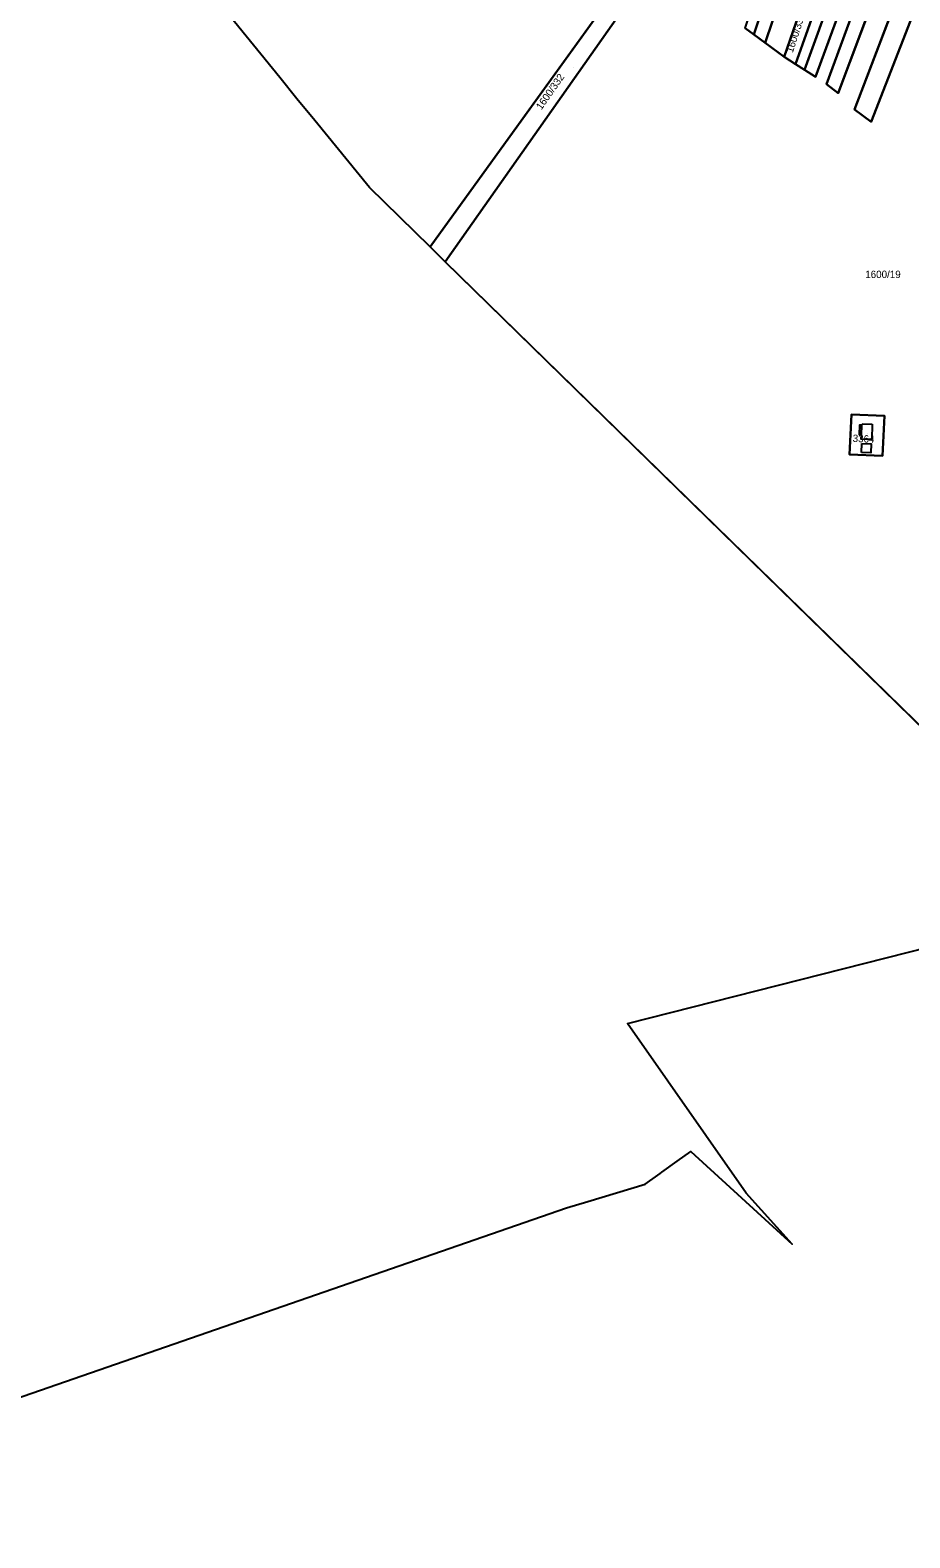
# Model space of a CAD drawing. Extents: x -262715 to -259381, y -1237238 to -1231182.
# Drawn here: x -262013.6 to -261773.9, y -1236768.6 to -1236357.8 of the extents above; entities that cross this region are included whole.
import ezdxf

# ---------------------------------------------------------------- set-up
doc = ezdxf.new("R2010")
doc.units = 0
for name, color, linetype in [('body_kn', 7, 'Continuous'), ('katuz_linie', 7, 'Continuous'), ('kladpar_druhypozemkov', 7, 'Continuous'), ('kladpar_hranice', 7, 'Continuous'), ('kladpar_parcelnecisla', 7, 'Continuous'), ('kladpar_plochy', 7, 'Continuous'), ('zappar_hrandruhpozemk', 7, 'Continuous'), ('zuob_linie', 7, 'Continuous'), ('zuob_plochy', 7, 'Continuous')]:
    doc.layers.add(name, color=color, linetype=linetype)

msp = doc.modelspace()

# ---------------------------------------------------------------- linework, layer by layer
at = {"layer": 'body_kn'}
for p, q in [((-261816.38, -1236359.01), (-261816.38, -1236359.01)), ((-261816.38, -1236359.01), (-261816.38, -1236359.01)), ((-261813.31, -1236361.3), (-261813.31, -1236361.3)), ((-261808.13, -1236365.09), (-261808.13, -1236365.09)), ((-261808.13, -1236365.09), (-261808.13, -1236365.09)), ((-261945.58, -1236370.74), (-261945.58, -1236370.74)), ((-261805.06, -1236367.11), (-261805.06, -1236367.11)), ((-261805.06, -1236367.11), (-261805.06, -1236367.11)), ((-261802.62, -1236368.65), (-261802.62, -1236368.65)), ((-261802.62, -1236368.65), (-261802.62, -1236368.65)), ((-261799.61, -1236370.59), (-261799.61, -1236370.59)), ((-261796.62, -1236372.52), (-261796.62, -1236372.52)), ((-261793.44, -1236375.02), (-261793.44, -1236375.02)), ((-261940.87, -1236376.52), (-261940.87, -1236376.52)), ((-261936.03, -1236382.46), (-261936.03, -1236382.46)), ((-261788.99, -1236379.43), (-261788.99, -1236379.43)), ((-261784.41, -1236382.82), (-261784.41, -1236382.82)), ((-261921.14, -1236400.73), (-261921.14, -1236400.73)), ((-261904.58, -1236416.92), (-261904.58, -1236416.92)), ((-261904.58, -1236416.92), (-261904.58, -1236416.92)), ((-261900.47, -1236420.93), (-261900.47, -1236420.93)), ((-261900.47, -1236420.93), (-261900.47, -1236420.93)), ((-261789.8, -1236462.53), (-261789.8, -1236462.53)), ((-261789.8, -1236462.53), (-261789.8, -1236462.53)), ((-261787.58, -1236465.44), (-261787.58, -1236465.44)), ((-261786.93, -1236465.47), (-261786.93, -1236465.47)), ((-261786.91, -1236465.07), (-261786.91, -1236465.07)), ((-261786.91, -1236465.07), (-261786.91, -1236465.07)), ((-261784.17, -1236465.2), (-261784.17, -1236465.2)), ((-261780.81, -1236462.96), (-261780.81, -1236462.96)), ((-261787.7, -1236468.04), (-261787.7, -1236468.04)), ((-261787.11, -1236469.27), (-261787.11, -1236469.27)), ((-261787.05, -1236468.07), (-261787.05, -1236468.07)), ((-261787.05, -1236468.07), (-261787.05, -1236468.07)), ((-261784.25, -1236469.35), (-261784.25, -1236469.35)), ((-261790.31, -1236473.43), (-261790.31, -1236473.43)), ((-261787.04, -1236472.92), (-261787.04, -1236472.92)), ((-261786.95, -1236470.43), (-261786.95, -1236470.43)), ((-261786.95, -1236470.43), (-261786.95, -1236470.43)), ((-261784.55, -1236473.01), (-261784.55, -1236473.01)), ((-261784.46, -1236470.52), (-261784.46, -1236470.52)), ((-261781.32, -1236473.84), (-261781.32, -1236473.84)), ((-261850.8, -1236628.52), (-261850.8, -1236628.52)), ((-261837.31, -1236666.04), (-261837.31, -1236666.04)), ((-261833.57, -1236663.38), (-261833.57, -1236663.38)), ((-261841.94, -1236669.33), (-261841.94, -1236669.33)), ((-261841.46, -1236668.99), (-261841.46, -1236668.99)), ((-261846.03, -1236672.24), (-261846.03, -1236672.24)), ((-261818.47, -1236674.69), (-261818.47, -1236674.69)), ((-261867.4, -1236678.73), (-261867.4, -1236678.73)), ((-261861.65, -1236676.99), (-261861.65, -1236676.99)), ((-261805.93, -1236688.64), (-261805.93, -1236688.64))]:
    msp.add_line(p, q, dxfattribs=at)
at = {"layer": 'katuz_linie'}
msp.add_lwpolyline([(-262126.94, -1236768.63), (-261867.4, -1236678.73), (-261861.65, -1236676.99), (-261846.03, -1236672.24), (-261841.94, -1236669.33), (-261841.46, -1236668.99), (-261837.31, -1236666.04), (-261833.57, -1236663.38), (-261805.93, -1236688.64), (-261818.47, -1236674.69), (-261850.8, -1236628.52), (-261721.65, -1236595.68), (-261900.47, -1236420.93), (-261904.58, -1236416.92), (-261921.14, -1236400.73), (-261936.03, -1236382.46), (-261940.87, -1236376.52), (-261945.58, -1236370.74), (-261959.9, -1236353.15)], dxfattribs=at)
at = {"layer": 'kladpar_druhypozemkov'}
for p, q in [((-261865.41, -1236367.96), (-261865.41, -1236367.96)), ((-261780.83, -1236423.34), (-261780.83, -1236423.34)), ((-261785.44, -1236467.68), (-261785.44, -1236467.68))]:
    msp.add_line(p, q, dxfattribs=at)
at = {"layer": 'kladpar_hranice'}
for p, q in [((-261808.13, -1236365.09), (-261801.51, -1236346.05)), ((-261802.62, -1236368.65), (-261805.06, -1236367.11)), ((-261900.47, -1236420.93), (-261904.58, -1236416.92))]:
    msp.add_line(p, q, dxfattribs=at)
for points in [[(-261768.56, -1236215.73), (-261783.95, -1236261.61), (-261786.4, -1236268.98), (-261799, -1236306.82), (-261816.38, -1236359.01), (-261818.71, -1236357.31), (-261806.34, -1236319.66), (-261793.09, -1236279.07), (-261791.2, -1236273.27), (-261782.26, -1236245.91), (-261770.94, -1236211.45)], [(-261760.95, -1236229.42), (-261776.87, -1236275.24), (-261791.73, -1236317.97), (-261793.71, -1236323.63), (-261801.51, -1236346.05), (-261808.13, -1236365.09), (-261813.31, -1236361.3), (-261799.22, -1236319.62), (-261785.48, -1236278.84), (-261780.28, -1236263.49), (-261765.79, -1236220.71)], [(-261805.06, -1236367.11), (-261798.34, -1236348.14), (-261790.42, -1236325.79), (-261788.42, -1236320.15), (-261758.08, -1236234.57), (-261756.75, -1236236.96), (-261755.57, -1236239.08), (-261802.62, -1236368.65)], [(-261752.96, -1236243.77), (-261799.61, -1236370.59), (-261802.62, -1236368.65), (-261755.57, -1236239.08), (-261752.96, -1236243.77)], [(-261818.71, -1236357.31), (-261816.38, -1236359.01), (-261813.31, -1236361.3), (-261808.13, -1236365.09), (-261805.06, -1236367.11), (-261802.62, -1236368.65), (-261799.61, -1236370.59), (-261752.96, -1236243.77)], [(-261747.63, -1236253.36), (-261752.99, -1236267.61), (-261774.9, -1236325.69), (-261793.44, -1236375.02), (-261796.62, -1236372.52), (-261777.07, -1236319.38), (-261750.57, -1236248.08)], [(-261816.38, -1236359.01), (-261799, -1236306.82), (-261786.4, -1236268.98), (-261780.28, -1236263.49), (-261785.48, -1236278.84), (-261799.22, -1236319.62), (-261813.31, -1236361.3), (-261816.38, -1236359.01)], [(-261739.65, -1236267.7), (-261745.69, -1236283.34), (-261784.41, -1236382.82), (-261788.99, -1236379.43), (-261776.5, -1236346.77), (-261759.45, -1236302.1), (-261743.61, -1236260.57)], [(-261776.5, -1236346.77), (-261788.99, -1236379.43), (-261784.41, -1236382.82), (-261745.69, -1236283.34)], [(-261777.07, -1236319.38), (-261796.62, -1236372.52), (-261793.44, -1236375.02), (-261774.9, -1236325.69)], [(-261904.58, -1236416.92), (-261921.14, -1236400.73), (-261936.03, -1236382.46), (-261940.87, -1236376.52), (-261945.58, -1236370.74), (-261959.9, -1236353.15), (-261963.58, -1236348.63), (-261970.73, -1236339.86), (-261974.76, -1236334.92), (-261980.15, -1236328.3), (-261984.07, -1236323.49)], [(-261904.58, -1236416.92), (-261847.89, -1236338.35), (-261844.27, -1236341), (-261900.47, -1236420.93)], [(-261900.47, -1236420.93), (-261844.27, -1236341), (-261847.89, -1236338.35), (-261904.58, -1236416.92)], [(-261798.34, -1236348.14), (-261805.06, -1236367.11), (-261808.13, -1236365.09)], [(-261694.06, -1236623.4), (-261721.65, -1236595.68), (-261900.47, -1236420.93)], [(-261789.8, -1236462.53), (-261780.81, -1236462.96), (-261781.32, -1236473.84), (-261790.31, -1236473.43), (-261789.8, -1236462.53)], [(-261780.81, -1236462.96), (-261789.8, -1236462.53), (-261790.31, -1236473.43), (-261781.32, -1236473.84), (-261780.81, -1236462.96)]]:
    msp.add_lwpolyline(points, dxfattribs=at)
at = {"layer": 'kladpar_plochy'}
for p, q in [((-261799.61, -1236370.59), (-261752.96, -1236243.77)), ((-261784.41, -1236382.82), (-261745.69, -1236283.34)), ((-261777.07, -1236319.38), (-261796.62, -1236372.52)), ((-261793.44, -1236375.02), (-261774.9, -1236325.69)), ((-261847.89, -1236338.35), (-261904.58, -1236416.92)), ((-261900.47, -1236420.93), (-261844.27, -1236341)), ((-261776.5, -1236346.77), (-261788.99, -1236379.43)), ((-261945.58, -1236370.74), (-261959.9, -1236353.15)), ((-261818.71, -1236357.31), (-261816.38, -1236359.01)), ((-261816.38, -1236359.01), (-261813.31, -1236361.3)), ((-261813.31, -1236361.3), (-261808.13, -1236365.09)), ((-261808.13, -1236365.09), (-261805.06, -1236367.11)), ((-261940.87, -1236376.52), (-261945.58, -1236370.74)), ((-261805.06, -1236367.11), (-261802.62, -1236368.65)), ((-261802.62, -1236368.65), (-261799.61, -1236370.59)), ((-261796.62, -1236372.52), (-261793.44, -1236375.02)), ((-261936.03, -1236382.46), (-261940.87, -1236376.52)), ((-261921.14, -1236400.73), (-261936.03, -1236382.46)), ((-261788.99, -1236379.43), (-261784.41, -1236382.82)), ((-261904.58, -1236416.92), (-261921.14, -1236400.73)), ((-261721.65, -1236595.68), (-261900.47, -1236420.93)), ((-261789.8, -1236462.53), (-261790.31, -1236473.43)), ((-261780.81, -1236462.96), (-261789.8, -1236462.53)), ((-261781.32, -1236473.84), (-261780.81, -1236462.96)), ((-261790.31, -1236473.43), (-261781.32, -1236473.84))]:
    msp.add_line(p, q, dxfattribs=at)
for points in [[(-261768.56, -1236215.73), (-261783.95, -1236261.61), (-261786.4, -1236268.98), (-261799, -1236306.82), (-261816.38, -1236359.01), (-261818.71, -1236357.31), (-261806.34, -1236319.66), (-261793.09, -1236279.07), (-261791.2, -1236273.27), (-261782.26, -1236245.91), (-261770.94, -1236211.45)], [(-261760.95, -1236229.42), (-261776.87, -1236275.24), (-261791.73, -1236317.97), (-261793.71, -1236323.63), (-261801.51, -1236346.05), (-261808.13, -1236365.09), (-261813.31, -1236361.3), (-261799.22, -1236319.62), (-261785.48, -1236278.84), (-261780.28, -1236263.49), (-261765.79, -1236220.71)], [(-261805.06, -1236367.11), (-261798.34, -1236348.14), (-261790.42, -1236325.79), (-261788.42, -1236320.15), (-261758.08, -1236234.57), (-261756.75, -1236236.96), (-261755.57, -1236239.08), (-261802.62, -1236368.65)], [(-261752.96, -1236243.77), (-261799.61, -1236370.59), (-261802.62, -1236368.65), (-261755.57, -1236239.08)], [(-261750.57, -1236248.08), (-261747.63, -1236253.36), (-261752.99, -1236267.61), (-261774.9, -1236325.69), (-261793.44, -1236375.02), (-261796.62, -1236372.52), (-261777.07, -1236319.38)], [(-261816.38, -1236359.01), (-261799, -1236306.82), (-261786.4, -1236268.98), (-261780.28, -1236263.49), (-261785.48, -1236278.84), (-261799.22, -1236319.62), (-261813.31, -1236361.3)], [(-261739.65, -1236267.7), (-261745.69, -1236283.34), (-261784.41, -1236382.82), (-261788.99, -1236379.43), (-261776.5, -1236346.77), (-261759.45, -1236302.1), (-261743.61, -1236260.57)], [(-261900.47, -1236420.93), (-261904.58, -1236416.92), (-261847.89, -1236338.35), (-261844.27, -1236341)], [(-261808.13, -1236365.09), (-261801.51, -1236346.05), (-261798.34, -1236348.14), (-261805.06, -1236367.11)], [(-261789.8, -1236462.53), (-261780.81, -1236462.96), (-261781.32, -1236473.84), (-261790.31, -1236473.43)]]:
    msp.add_lwpolyline(points, close=True, dxfattribs=at)
at = {"layer": 'zappar_hrandruhpozemk'}
for p, q in [((-261787.05, -1236468.07), (-261786.93, -1236465.47)), ((-261786.93, -1236465.47), (-261786.91, -1236465.07)), ((-261786.91, -1236465.07), (-261784.17, -1236465.2)), ((-261784.17, -1236465.2), (-261784.25, -1236469.35)), ((-261787.04, -1236472.92), (-261786.95, -1236470.43))]:
    msp.add_line(p, q, dxfattribs=at)
for points in [[(-261786.93, -1236465.47), (-261787.58, -1236465.44), (-261787.7, -1236468.04), (-261787.05, -1236468.07)], [(-261784.25, -1236469.35), (-261787.11, -1236469.27), (-261787.05, -1236468.07)], [(-261786.95, -1236470.43), (-261784.46, -1236470.52), (-261784.55, -1236473.01), (-261787.04, -1236472.92)]]:
    msp.add_lwpolyline(points, dxfattribs=at)
at = {"layer": 'zuob_linie'}
msp.add_lwpolyline([(-262126.94, -1236768.63), (-261867.4, -1236678.73), (-261861.65, -1236676.99), (-261846.03, -1236672.24), (-261841.94, -1236669.33), (-261841.46, -1236668.99), (-261837.31, -1236666.04), (-261833.57, -1236663.38), (-261805.93, -1236688.64), (-261818.47, -1236674.69), (-261850.8, -1236628.52), (-261721.65, -1236595.68), (-261900.47, -1236420.93), (-261904.58, -1236416.92), (-261921.14, -1236400.73), (-261936.03, -1236382.46), (-261940.87, -1236376.52), (-261945.58, -1236370.74), (-261959.9, -1236353.15)], dxfattribs=at)
at = {"layer": 'zuob_plochy'}
msp.add_lwpolyline([(-262126.94, -1236768.63), (-261867.4, -1236678.73), (-261861.65, -1236676.99), (-261846.03, -1236672.24), (-261841.94, -1236669.33), (-261841.46, -1236668.99), (-261837.31, -1236666.04), (-261833.57, -1236663.38), (-261805.93, -1236688.64), (-261818.47, -1236674.69), (-261850.8, -1236628.52), (-261721.65, -1236595.68), (-261900.47, -1236420.93), (-261904.58, -1236416.92), (-261921.14, -1236400.73), (-261936.03, -1236382.46), (-261940.87, -1236376.52), (-261945.58, -1236370.74), (-261959.9, -1236353.15)], dxfattribs=at)

# ---------------------------------------------------------------- texts
at = {"layer": 'kladpar_parcelnecisla'}
for s, rotation, p in [('1600/336', 72, (-261805.78, -1236364.14)), ('1600/332', 55, (-261874.28, -1236379.71)), ('3364', 357, (-261789.5, -1236470))]:
    msp.add_text(s, height=2, rotation=rotation, dxfattribs=at).set_placement(p)
msp.add_text('1600/19', height=2, dxfattribs=at).set_placement((-261786.03, -1236425.38))

doc.saveas('drawing.dxf')
